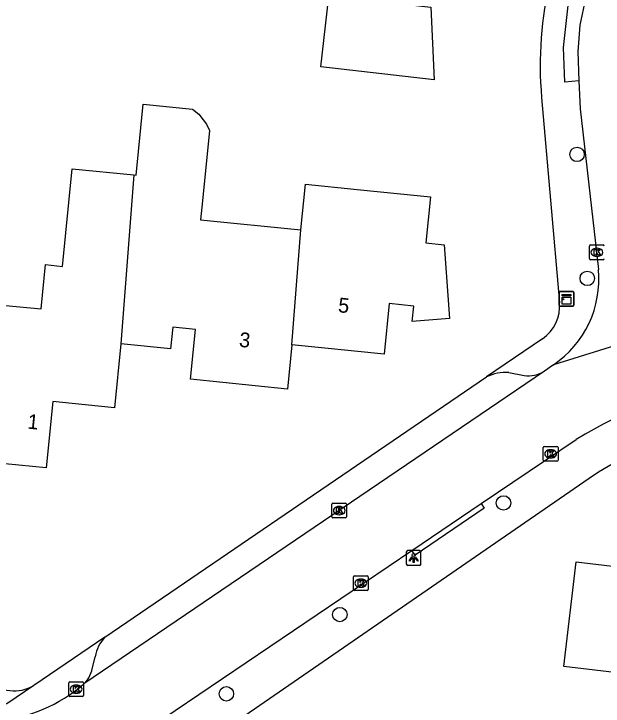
# Model space of a CAD drawing. Extents: x 162398 to 163643, y 386453 to 387397.
# Drawn here: x 162947.59 to 162987.55, y 386536.91 to 386583.81 of the extents above; entities that cross this region are included whole.
import ezdxf

# ---------------------------------------------------------------- set-up
doc = ezdxf.new("R2010")
doc.units = 0
for name, color, linetype in [('IMGEO_Boom', 7, 'Continuous'), ('IMGEO_Groenvoorziening', 7, 'Continuous'), ('IMGEO_Kast', 7, 'Continuous'), ('IMGEO_Kolk', 7, 'Continuous'), ('IMGEO_Lichtpunt', 7, 'Continuous'), ('IMGEO_Pand', 7, 'Continuous'), ('IMGEO_Pand_nummerreeks', 7, 'Continuous'), ('IMGEO_Parkeervlak_open', 7, 'Continuous'), ('IMGEO_Rijbaan_lokaal_open', 7, 'Continuous'), ('IMGEO_Voetpad_open', 7, 'Continuous')]:
    doc.layers.add(name, color=color, linetype=linetype)

msp = doc.modelspace()

# ---------------------------------------------------------------- linework, layer by layer
at = {"layer": 'IMGEO_Boom'}
for centre in [(162985.781, 386574.289), (162986.473, 386565.885), (162980.795, 386550.678), (162969.697, 386543.115), (162962.005, 386537.745)]:
    msp.add_circle(centre, 0.489, dxfattribs=at)
at = {"layer": 'IMGEO_Groenvoorziening'}
msp.add_arc((162947.632, 386540.472), 2.526, 224.7446, 301.5264, dxfattribs=at)
at = {"layer": 'IMGEO_Kast'}
for p, q in [((162984.567, 386564.082), (162984.567, 386564.923)), ((162984.567, 386564.923), (162984.567, 386564.082)), ((162984.642, 386565.007), (162985.483, 386565.007)), ((162985.483, 386565.007), (162984.642, 386565.007)), ((162985.567, 386564.932), (162985.567, 386564.091)), ((162985.567, 386564.091), (162985.567, 386564.932)), ((162985.492, 386564.007), (162984.651, 386564.007)), ((162984.651, 386564.007), (162985.492, 386564.007))]:
    msp.add_line(p, q, dxfattribs=at)
for points in [[(162984.762, 386564.797), (162985.362, 386564.797), (162985.362, 386564.712), (162984.762, 386564.712), (162984.762, 386564.797)], [(162984.762, 386564.622), (162985.362, 386564.622), (162985.362, 386564.133), (162984.762, 386564.133), (162984.762, 386564.622)]]:
    msp.add_lwpolyline(points, dxfattribs=at)
msp.add_circle((162984.846, 386564.471), 0.0377, dxfattribs=at)
for centre, start, end in [((162984.645, 386564.929), 92.4484, 184.2845), ((162984.645, 386564.929), 92.4484, 184.2845), ((162985.489, 386564.929), 2.4484, 94.2845), ((162985.489, 386564.929), 2.4484, 94.2845), ((162984.645, 386564.085), 182.4484, 274.2845), ((162984.645, 386564.085), 182.4484, 274.2845), ((162985.489, 386564.085), 272.4484, 4.2845), ((162985.489, 386564.085), 272.4484, 4.2845)]:
    msp.add_arc(centre, 0.0779, start, end, dxfattribs=at)
at = {"layer": 'IMGEO_Kolk'}
for p, q in [((162986.699, 386568.153), (162987.551, 386568.153)), ((162986.624, 386567.227), (162986.624, 386568.079)), ((162987.112, 386567.933), (162987.137, 386567.933)), ((162987.135, 386567.373), (162987.11, 386567.373)), ((162987.551, 386567.153), (162986.699, 386567.153)), ((162983.489, 386553.577), (162983.489, 386554.429)), ((162983.564, 386554.503), (162984.416, 386554.503)), ((162983.977, 386554.283), (162984.002, 386554.283)), ((162984.49, 386554.429), (162984.49, 386553.577)), ((162984, 386553.723), (162983.975, 386553.723)), ((162984.416, 386553.503), (162983.564, 386553.503)), ((162969.156, 386549.732), (162969.156, 386550.584)), ((162969.231, 386550.658), (162970.083, 386550.658)), ((162969.644, 386550.438), (162969.669, 386550.438)), ((162970.157, 386550.584), (162970.157, 386549.732)), ((162969.667, 386549.878), (162969.642, 386549.878)), ((162970.083, 386549.658), (162969.231, 386549.658)), ((162970.616, 386544.816), (162970.616, 386545.668)), ((162970.691, 386545.742), (162971.543, 386545.742)), ((162971.617, 386545.668), (162971.617, 386544.816)), ((162971.104, 386545.522), (162971.129, 386545.522)), ((162971.543, 386544.742), (162970.691, 386544.742)), ((162971.127, 386544.962), (162971.102, 386544.962)), ((162951.313, 386537.635), (162951.313, 386538.487)), ((162951.388, 386538.561), (162952.24, 386538.561)), ((162951.801, 386538.341), (162951.826, 386538.341)), ((162952.314, 386538.487), (162952.314, 386537.635)), ((162951.824, 386537.781), (162951.799, 386537.781)), ((162952.24, 386537.561), (162951.388, 386537.561))]:
    msp.add_line(p, q, dxfattribs=at)
for points in [[(162986.699, 386568.153), (162987.551, 386568.153)], [(162986.624, 386567.227), (162986.624, 386568.079)], [(162986.945, 386567.853), (162987.068, 386567.853), (162987.068, 386567.702), (162987.198, 386567.853), (162987.362, 386567.853), (162987.216, 386567.702), (162987.369, 386567.453), (162987.217, 386567.453), (162987.132, 386567.617), (162987.068, 386567.55), (162987.068, 386567.453), (162986.945, 386567.453), (162986.945, 386567.853)], [(162987.551, 386567.153), (162986.699, 386567.153)], [(162983.489, 386553.577), (162983.489, 386554.429)], [(162983.564, 386554.503), (162984.416, 386554.503)], [(162983.81, 386554.203), (162983.933, 386554.203), (162983.933, 386554.052), (162984.063, 386554.203), (162984.227, 386554.203), (162984.081, 386554.052), (162984.234, 386553.803), (162984.082, 386553.803), (162983.997, 386553.967), (162983.933, 386553.9), (162983.933, 386553.803), (162983.81, 386553.803), (162983.81, 386554.203)], [(162984.49, 386554.429), (162984.49, 386553.577)], [(162984.416, 386553.503), (162983.564, 386553.503)], [(162969.156, 386549.732), (162969.156, 386550.584)], [(162969.231, 386550.658), (162970.083, 386550.658)], [(162969.477, 386550.358), (162969.6, 386550.358), (162969.6, 386550.207), (162969.73, 386550.358), (162969.894, 386550.358), (162969.748, 386550.207), (162969.901, 386549.958), (162969.749, 386549.958), (162969.664, 386550.122), (162969.6, 386550.055), (162969.6, 386549.958), (162969.477, 386549.958), (162969.477, 386550.358)], [(162970.157, 386550.584), (162970.157, 386549.732)], [(162970.083, 386549.658), (162969.231, 386549.658)], [(162970.616, 386544.816), (162970.616, 386545.668)], [(162970.691, 386545.742), (162971.543, 386545.742)], [(162971.617, 386545.668), (162971.617, 386544.816)], [(162970.937, 386545.442), (162971.06, 386545.442), (162971.06, 386545.291), (162971.19, 386545.442), (162971.354, 386545.442), (162971.208, 386545.291), (162971.361, 386545.042), (162971.209, 386545.042), (162971.124, 386545.206), (162971.06, 386545.139), (162971.06, 386545.042), (162970.937, 386545.042), (162970.937, 386545.442)], [(162971.543, 386544.742), (162970.691, 386544.742)], [(162951.313, 386537.635), (162951.313, 386538.487)], [(162951.388, 386538.561), (162952.24, 386538.561)], [(162951.634, 386538.261), (162951.757, 386538.261), (162951.757, 386538.11), (162951.887, 386538.261), (162952.051, 386538.261), (162951.905, 386538.11), (162952.058, 386537.861), (162951.906, 386537.861), (162951.821, 386538.025), (162951.757, 386537.958), (162951.757, 386537.861), (162951.634, 386537.861), (162951.634, 386538.261)], [(162952.314, 386538.487), (162952.314, 386537.635)], [(162952.24, 386537.561), (162951.388, 386537.561)]]:
    msp.add_lwpolyline(points, dxfattribs=at)
for centre, start, end in [((162986.701, 386568.077), 91.552, 178.448), ((162986.701, 386568.077), 91.552, 178.448), ((162987.549, 386568.077), 1.552, 88.448), ((162987.549, 386568.077), 1.552, 88.448), ((162986.701, 386567.229), 181.552, 268.448), ((162986.701, 386567.229), 181.552, 268.448), ((162987.549, 386567.229), 271.552, 358.448), ((162987.549, 386567.229), 271.552, 358.448), ((162983.566, 386554.427), 91.552, 178.448), ((162983.566, 386554.427), 91.552, 178.448), ((162984.414, 386554.427), 1.552, 88.448), ((162984.414, 386554.427), 1.552, 88.448), ((162983.566, 386553.579), 181.552, 268.448), ((162983.566, 386553.579), 181.552, 268.448), ((162984.414, 386553.579), 271.552, 358.448), ((162984.414, 386553.579), 271.552, 358.448), ((162969.233, 386550.582), 91.552, 178.448), ((162969.233, 386550.582), 91.552, 178.448), ((162970.081, 386550.582), 1.552, 88.448), ((162970.081, 386550.582), 1.552, 88.448), ((162969.233, 386549.734), 181.552, 268.448), ((162969.233, 386549.734), 181.552, 268.448), ((162970.081, 386549.734), 271.552, 358.448), ((162970.081, 386549.734), 271.552, 358.448), ((162970.693, 386545.666), 91.552, 178.448), ((162970.693, 386545.666), 91.552, 178.448), ((162971.541, 386545.666), 1.552, 88.448), ((162971.541, 386545.666), 1.552, 88.448), ((162970.693, 386544.818), 181.552, 268.448), ((162970.693, 386544.818), 181.552, 268.448), ((162971.541, 386544.818), 271.552, 358.448), ((162971.541, 386544.818), 271.552, 358.448), ((162951.39, 386538.485), 91.552, 178.448), ((162951.39, 386538.485), 91.552, 178.448), ((162952.238, 386538.485), 1.552, 88.448), ((162952.238, 386538.485), 1.552, 88.448), ((162951.39, 386537.637), 181.552, 268.448), ((162951.39, 386537.637), 181.552, 268.448), ((162952.238, 386537.637), 271.552, 358.448), ((162952.238, 386537.637), 271.552, 358.448)]:
    msp.add_arc(centre, 0.0765, start, end, dxfattribs=at)
for centre, major_axis, ratio, start_param, end_param in [((162987.111, 386567.653), (-0.387, 0.002), 0.722429, 4.712389, 7.853982), ((162987.136, 386567.653), (-0.39, 0.002), 0.717154, 1.570796, 4.712389), ((162983.976, 386554.003), (-0.387, 0.002), 0.722429, 4.712389, 7.853982), ((162984.001, 386554.003), (-0.39, 0.002), 0.717154, 1.570796, 4.712389), ((162969.643, 386550.158), (-0.387, 0.002), 0.722429, 4.712389, 7.853982), ((162969.668, 386550.158), (-0.39, 0.002), 0.717154, 1.570796, 4.712389), ((162971.103, 386545.242), (-0.387, 0.002), 0.722429, 4.712389, 7.853982), ((162971.128, 386545.242), (-0.39, 0.002), 0.717154, 1.570796, 4.712389), ((162951.8, 386538.061), (-0.387, 0.002), 0.722429, 4.712389, 7.853982), ((162951.825, 386538.061), (-0.39, 0.002), 0.717154, 1.570796, 4.712389)]:
    msp.add_ellipse(centre, major_axis=major_axis, ratio=ratio, start_param=start_param, end_param=end_param, dxfattribs=at)
at = {"layer": 'IMGEO_Lichtpunt'}
for p, q in [((162974.203, 386547.351), (162974.203, 386546.544)), ((162974.203, 386547.351), (162974.203, 386546.544)), ((162975.105, 386547.446), (162974.297, 386547.446)), ((162975.105, 386547.446), (162974.297, 386547.446)), ((162975.199, 386546.544), (162975.199, 386547.351)), ((162975.199, 386546.544), (162975.199, 386547.351)), ((162974.297, 386546.45), (162975.105, 386546.45)), ((162974.297, 386546.45), (162975.105, 386546.45))]:
    msp.add_line(p, q, dxfattribs=at)
for points in [[(162974.577, 386547.015), (162974.616, 386546.987), (162974.428, 386546.725), (162974.39, 386546.752), (162974.577, 386547.015)], [(162974.679, 386546.967), (162974.726, 386546.967), (162974.726, 386546.645), (162974.679, 386546.645), (162974.679, 386546.967)], [(162974.789, 386546.987), (162974.827, 386547.014), (162975.014, 386546.752), (162974.975, 386546.724), (162974.789, 386546.987)]]:
    msp.add_lwpolyline(points, dxfattribs=at)
msp.add_circle((162974.702, 386547.149), 0.0994, dxfattribs=at)
for centre, start, end in [((162974.297, 386547.351), 90, 180), ((162974.297, 386547.351), 90, 180), ((162975.105, 386547.351), 0, 90), ((162975.105, 386547.351), 0, 90), ((162974.297, 386546.544), 180, 270), ((162974.297, 386546.544), 180, 270), ((162975.105, 386546.544), 270, 0), ((162975.105, 386546.544), 270, 360)]:
    msp.add_arc(centre, 0.0946, start, end, dxfattribs=at)
at = {"layer": 'IMGEO_Pand'}
for points in [[(162974.641, 386584.395), (162975.858, 386584.257), (162976.095, 386579.343), (162968.413, 386580.213), (162968.957, 386585.013)], [(162955.735, 386572.897), (162955.886, 386572.881), (162956.37, 386577.69), (162959.704, 386577.355), (162960.125, 386577.003), (162960.42, 386576.626), (162960.65, 386576.337), (162960.856, 386575.907), (162960.377, 386571.144), (162960.248, 386569.862), (162967.058, 386569.177)], [(162943.37, 386563.251), (162946.902, 386562.896), (162947.019, 386564.058), (162949.438, 386563.815), (162949.74, 386566.819), (162950.889, 386566.703), (162951.555, 386573.318), (162955.735, 386572.897)], [(162955.735, 386572.897), (162954.845, 386561.445)], [(162967.058, 386569.177), (162967.368, 386572.262), (162970.86, 386571.911), (162975.834, 386571.41), (162975.52, 386568.292), (162976.769, 386568.166), (162977.122, 386563.16), (162974.596, 386562.964), (162974.702, 386564.014), (162973.044, 386564.18), (162972.699, 386560.752), (162966.436, 386561.382)], [(162966.436, 386561.382), (162967.058, 386569.177)], [(162966.436, 386561.382), (162966.136, 386558.393), (162959.575, 386559.052), (162959.914, 386562.424), (162958.361, 386562.581), (162958.213, 386561.106), (162954.845, 386561.445)], [(162954.845, 386561.445), (162954.411, 386557.117), (162951.55, 386557.406), (162950.235, 386557.539), (162949.784, 386553.051), (162947, 386553.331), (162946.89, 386552.235), (162942.099, 386552.717), (162942.495, 386556.654)], [(163001.321, 386542.76), (163001.052, 386540.228), (162998.472, 386540.537), (162997.774, 386534.71), (162997.227, 386530.143), (162993.138, 386530.633), (162993.342, 386532.335), (162993.003, 386532.376), (162993.071, 386532.95), (162988.786, 386533.463), (162988.714, 386532.864), (162988.339, 386532.909), (162989.079, 386539.091), (162984.88, 386539.594), (162985.731, 386546.698), (162992.373, 386545.903), (162992.279, 386545.12), (162994.506, 386544.853), (162994.732, 386546.737), (162999.151, 386546.208), (162999.218, 386546.769), (163001.714, 386546.47)]]:
    msp.add_lwpolyline(points, dxfattribs=at)
at = {"layer": 'IMGEO_Parkeervlak_open'}
msp.add_lwpolyline([(162953.76, 386541.592), (162979.633, 386559.214)], dxfattribs=at)
at = {"layer": 'IMGEO_Rijbaan_lokaal_open'}
for points in [[(162986.792, 386586.51), (162986.345, 386584.869), (162985.979, 386583.049), (162985.823, 386581.259), (162985.89, 386579.268)], [(162985.89, 386579.268), (162986.002, 386577.374), (162987.233, 386566.49)], [(162997.394, 386564.134), (162984.188, 386560.035)], [(162984.188, 386560.035), (162983.567, 386559.613)], [(162983.567, 386559.613), (162952.347, 386538.426)], [(162979.274, 386550.644), (162985.729, 386554.969)], [(162974.583, 386547.456), (162979.274, 386550.644)], [(162953.159, 386532.714), (162956.926, 386535.522), (162974.583, 386547.456)]]:
    msp.add_lwpolyline(points, dxfattribs=at)
for centre, radius, start, end in [((162980.242, 386565.842), 7.021, 304.1974, 5.2936), ((163002.493, 386527.535), 32.151, 101.4911, 121.4273), ((162945.377, 386546.492), 10.66, 275.62, 310.8308)]:
    msp.add_arc(centre, radius, start, end, dxfattribs=at)
at = {"layer": 'IMGEO_Voetpad_open'}
for points in [[(162985.89, 386579.268), (162984.942, 386579.186), (162984.861, 386581.535), (162985.233, 386584.802), (162985.806, 386586.689), (162986.792, 386586.51)], [(162983.377, 386578.134), (162984.592, 386564.243)], [(162983.432, 386561.801), (162979.633, 386559.214)], [(162981.159, 386559.506), (162982.189, 386559.3)], [(162986.613, 386552.337), (162956.568, 386531.651), (162956.419, 386531.52)], [(162979.274, 386550.644), (162979.481, 386550.332), (162974.793, 386547.141), (162974.583, 386547.456)], [(162953.76, 386541.592), (162948.953, 386538.319)], [(162952.347, 386538.426), (162952.467, 386538.551), (162952.575, 386538.687), (162952.671, 386538.831), (162952.754, 386538.984), (162952.822, 386539.143), (162952.876, 386539.308), (162952.879, 386539.318), (162953.111, 386540.26)], [(162948.953, 386538.319), (162947.123, 386537.071), (162947.08, 386537.042)]]:
    msp.add_lwpolyline(points, dxfattribs=at)
for centre, radius, start, end in [((163008.512, 386580.334), 25.231, 148.3699, 185.0018), ((162981.934, 386564.009), 2.669, 304.1585, 5.0241), ((162980.96, 386556.41), 3.102, 86.3304, 115.3348), ((162982.441, 386561.38), 2.095, 263.0882, 302.5059), ((162999.707, 386533.256), 23.142, 94.5488, 124.46), ((162955.736, 386539.805), 2.664, 137.8741, 170.1718)]:
    msp.add_arc(centre, radius, start, end, dxfattribs=at)

# ---------------------------------------------------------------- texts
at = {"layer": 'IMGEO_Pand_nummerreeks'}
for s, rotation, p in [('5', 354.2559, (162969.546, 386563.601)), ('3', 354.2643, (162962.833, 386561.257)), ('1', 354.2568, (162948.483, 386555.714))]:
    msp.add_text(s, height=1, rotation=rotation, dxfattribs=at).set_placement(p)

doc.saveas('drawing.dxf')
